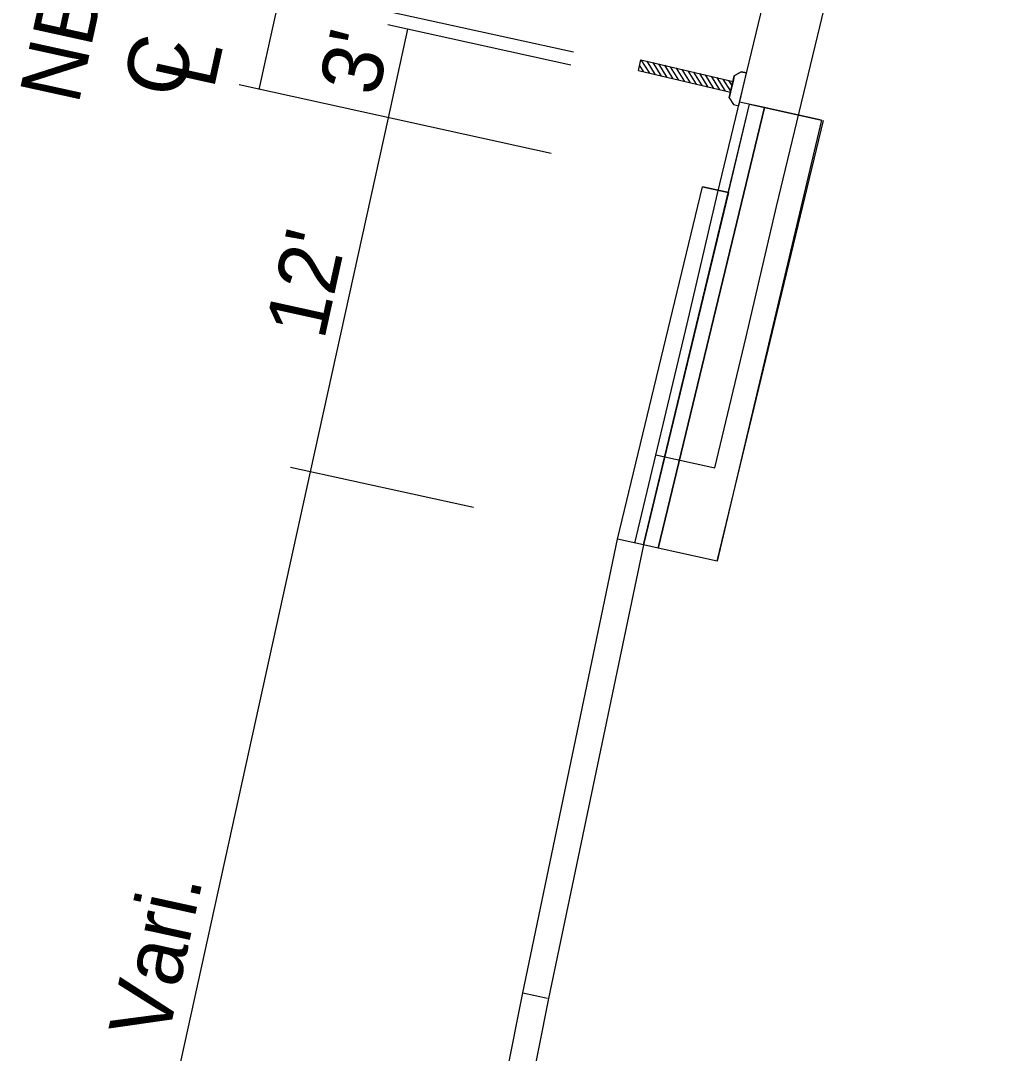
# Model space of a CAD drawing. Extents: x 14104283 to 14120882, y 8635219 to 8671666.
# Drawn here: x 14107430.7 to 14107562.1, y 8639383.1 to 8639519.9 of the extents above; entities that cross this region are included whole.
import ezdxf

# ---------------------------------------------------------------- set-up
doc = ezdxf.new("R2010")
doc.units = 0
for name, color, linetype in [('Cell', 7, 'Continuous'), ('dsnShadingPaved', 7, 'Continuous'), ('dsnTextFinalPlan', 7, 'Continuous'), ('TC_ShoulderPCC', 7, 'Continuous'), ('TC_Subbase', 7, 'Continuous'), ('TC_SubgradeTreatment', 7, 'Continuous'), ('TC_SubstrataExistingPavement', 7, 'Continuous'), ('Terrain', 7, 'Continuous')]:
    doc.layers.add(name, color=color, linetype=linetype)

msp = doc.modelspace()

# ---------------------------------------------------------------- linework, layer by layer
at = {"layer": 'Cell'}
for p, q in [((14107512.49, 8639513.26), (14107512.83, 8639514.7)), ((14107513.22, 8639513.09), (14107512.66, 8639513.99)), ((14107512.83, 8639514.7), (14107525.02, 8639511.84)), ((14107513.99, 8639512.91), (14107512.88, 8639514.69)), ((14107514.76, 8639512.72), (14107513.66, 8639514.51)), ((14107515.54, 8639512.54), (14107514.43, 8639514.33)), ((14107516.31, 8639512.36), (14107515.2, 8639514.15)), ((14107517.08, 8639512.18), (14107515.98, 8639513.97)), ((14107517.85, 8639512), (14107516.75, 8639513.78)), ((14107518.63, 8639511.82), (14107517.52, 8639513.6)), ((14107519.4, 8639511.63), (14107518.29, 8639513.42)), ((14107512.49, 8639513.26), (14107524.68, 8639510.39)), ((14107520.17, 8639511.45), (14107519.07, 8639513.24)), ((14107520.95, 8639511.27), (14107519.84, 8639513.06)), ((14107521.72, 8639511.09), (14107520.61, 8639512.87)), ((14107522.49, 8639510.91), (14107521.39, 8639512.69)), ((14107523.27, 8639510.73), (14107522.16, 8639512.51)), ((14107524.04, 8639510.54), (14107522.93, 8639512.33)), ((14107524.71, 8639510.52), (14107523.71, 8639512.15)), ((14107524.51, 8639509.67), (14107525.19, 8639512.56)), ((14107525.19, 8639512.56), (14107525.02, 8639511.84)), ((14107526.08, 8639513.11), (14107525.19, 8639512.56)), ((14107525.19, 8639512.56), (14107526.08, 8639513.11)), ((14107525.78, 8639508.61), (14107526.8, 8639512.95)), ((14107525.78, 8639508.61), (14107526.8, 8639512.95)), ((14107526.8, 8639512.95), (14107526.08, 8639513.11)), ((14107526.08, 8639513.11), (14107526.8, 8639512.95)), ((14107524.9, 8639511.29), (14107524.48, 8639511.97)), ((14107525.02, 8639511.84), (14107524.68, 8639510.39)), ((14107524.68, 8639510.39), (14107524.51, 8639509.67)), ((14107524.51, 8639509.67), (14107525.06, 8639508.78)), ((14107524.51, 8639509.67), (14107525.06, 8639508.78)), ((14107525.06, 8639508.78), (14107525.78, 8639508.61)), ((14107525.06, 8639508.78), (14107525.78, 8639508.61))]:
    msp.add_line(p, q, dxfattribs=at)
at = {"layer": 'dsnShadingPaved'}
for points in [[(14107513.16, 8639450.46), (14107527.22, 8639508.8), (14107529.18, 8639508.37), (14107515.12, 8639450.03)], [(14107515.12, 8639450.03), (14107529.18, 8639508.37), (14107536.75, 8639506.71), (14107522.93, 8639448.31)], [(14107509.74, 8639451.2), (14107520.99, 8639497.88), (14107524.41, 8639497.13), (14107513.16, 8639450.46)]]:
    msp.add_lwpolyline(points, close=True, dxfattribs=at)
at = {"layer": 'dsnTextFinalPlan'}
for p, q in [((14107462.3, 8639510.78), (14107478.12, 8639582.79)), ((14107503.91, 8639515.7), (14107479.69, 8639521.02)), ((14107503.53, 8639514), (14107479.31, 8639519.33)), ((14107479.41, 8639507.02), (14107481.98, 8639518.74)), ((14107500.96, 8639502.28), (14107459.63, 8639511.37)), ((14107469.11, 8639460.14), (14107479.41, 8639507.02)), ((14107440.25, 8639328.81), (14107469.11, 8639460.14)), ((14107490.66, 8639455.4), (14107466.44, 8639460.72))]:
    msp.add_line(p, q, dxfattribs=at)
at = {"layer": 'TC_ShoulderPCC'}
for p, q in [((14107509.74, 8639451.2), (14107520.99, 8639497.88)), ((14107513.16, 8639450.46), (14107524.41, 8639497.13)), ((14107524.41, 8639497.13), (14107520.99, 8639497.88)), ((14107513.16, 8639450.45), (14107509.74, 8639451.2))]:
    msp.add_line(p, q, dxfattribs=at)
at = {"layer": 'TC_Subbase'}
for p, q in [((14107515.12, 8639450.03), (14107529.18, 8639508.37)), ((14107524.41, 8639497.13), (14107527.22, 8639508.8)), ((14107529.18, 8639508.37), (14107525.89, 8639509.09)), ((14107515.12, 8639450.03), (14107513.16, 8639450.46))]:
    msp.add_line(p, q, dxfattribs=at)
at = {"layer": 'TC_SubgradeTreatment'}
for p, q in [((14107536.75, 8639506.71), (14107529.18, 8639508.37)), ((14107522.93, 8639448.31), (14107536.99, 8639506.65)), ((14107522.93, 8639448.31), (14107515.12, 8639450.03))]:
    msp.add_line(p, q, dxfattribs=at)
at = {"layer": 'TC_SubstrataExistingPavement'}
for p, q in [((14107514.8, 8639462.38), (14107522.61, 8639460.67)), ((14107513.16, 8639450.46), (14107509.74, 8639451.21)), ((14107497.18, 8639391.15), (14107500.47, 8639390.42))]:
    msp.add_line(p, q, dxfattribs=at)
for points in [[(14107522.61, 8639460.67), (14107526.76, 8639478.03), (14107530.78, 8639495.26), (14107539.21, 8639530.27), (14107543.78, 8639548.94), (14107549.33, 8639568.6), (14107552.24, 8639578.79)], [(14107513.16, 8639450.46), (14107500.59, 8639390.4), (14107481.87, 8639296.22), (14107478.45, 8639296.97)]]:
    msp.add_lwpolyline(points, dxfattribs=at)
at = {"layer": 'Terrain'}
for points in [[(14107512, 8639450.67), (14107518.95, 8639479.75), (14107522.97, 8639496.97), (14107531.4, 8639531.98), (14107535.97, 8639550.66), (14107541.52, 8639570.32), (14107544.43, 8639580.51), (14107559.65, 8639602.7), (14107562.12, 8639606.47)], [(14107471.43, 8639257.56), (14107478.45, 8639296.97), (14107497.18, 8639391.15), (14107509.74, 8639451.21)]]:
    msp.add_lwpolyline(points, dxfattribs=at)

# ---------------------------------------------------------------- texts
at = {"layer": 'dsnTextFinalPlan'}
for s, p in [('NB', (14107438.35, 8639508.62)), ('C', (14107452, 8639509.33)), ("3'", (14107477.97, 8639509.69)), ('L', (14107456.26, 8639510.64)), ("12'", (14107470.88, 8639477.44)), ('Vari.', (14107450.15, 8639384.65))]:
    msp.add_text(s, height=8, rotation=77.6078, dxfattribs=at).set_placement(p)

doc.saveas('drawing.dxf')
